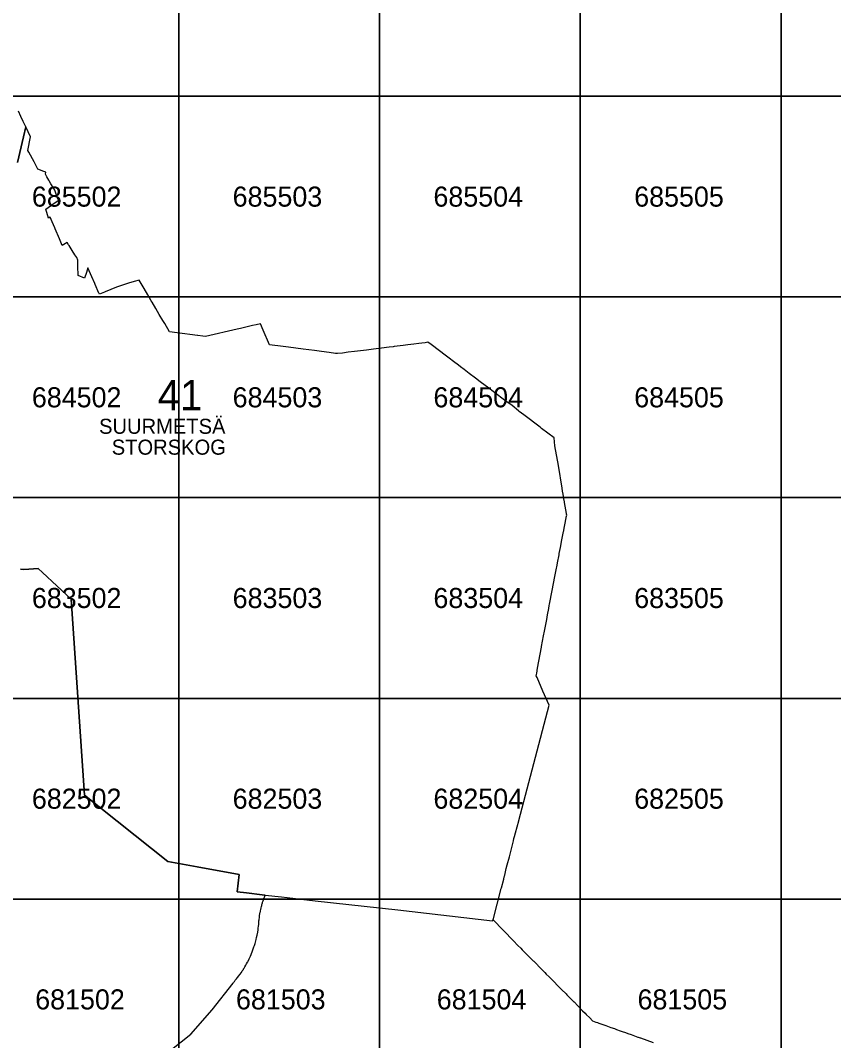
# Model space of a CAD drawing. Extents: x 25485000 to 25520000, y 6656775 to 6690000.
# Drawn here: x 25502211 to 25506262, y 6681295 to 6686378 of the extents above; entities that cross this region are included whole.
import ezdxf

# ---------------------------------------------------------------- set-up
doc = ezdxf.new("R2010")
doc.units = 0
doc.layers.add('Level 63', color=7, linetype='Continuous')

msp = doc.modelspace()

# ---------------------------------------------------------------- linework, layer by layer
at = {"layer": 'Level 63'}
for points in [[(25502000, 6686000), (25503000, 6686000), (25503000, 6687000), (25502000, 6687000)], [(25503000, 6686000), (25504000, 6686000), (25504000, 6687000), (25503000, 6687000)], [(25504000, 6686000), (25505000, 6686000), (25505000, 6687000), (25504000, 6687000)], [(25505000, 6686000), (25506000, 6686000), (25506000, 6687000), (25505000, 6687000)], [(25506000, 6686000), (25507000, 6686000), (25507000, 6687000), (25506000, 6687000)], [(25502000, 6685000), (25503000, 6685000), (25503000, 6686000), (25502000, 6686000)], [(25503000, 6685000), (25504000, 6685000), (25504000, 6686000), (25503000, 6686000)], [(25504000, 6685000), (25505000, 6685000), (25505000, 6686000), (25504000, 6686000)], [(25505000, 6685000), (25506000, 6685000), (25506000, 6686000), (25505000, 6686000)], [(25506000, 6685000), (25507000, 6685000), (25507000, 6686000), (25506000, 6686000)], [(25502000, 6684000), (25503000, 6684000), (25503000, 6685000), (25502000, 6685000)], [(25503000, 6684000), (25504000, 6684000), (25504000, 6685000), (25503000, 6685000)], [(25504000, 6684000), (25505000, 6684000), (25505000, 6685000), (25504000, 6685000)], [(25505000, 6684000), (25506000, 6684000), (25506000, 6685000), (25505000, 6685000)], [(25506000, 6684000), (25507000, 6684000), (25507000, 6685000), (25506000, 6685000)], [(25502000, 6683000), (25503000, 6683000), (25503000, 6684000), (25502000, 6684000)], [(25503000, 6683000), (25504000, 6683000), (25504000, 6684000), (25503000, 6684000)], [(25504000, 6683000), (25505000, 6683000), (25505000, 6684000), (25504000, 6684000)], [(25505000, 6683000), (25506000, 6683000), (25506000, 6684000), (25505000, 6684000)], [(25506000, 6683000), (25507000, 6683000), (25507000, 6684000), (25506000, 6684000)], [(25502000, 6682000), (25503000, 6682000), (25503000, 6683000), (25502000, 6683000)], [(25503000, 6682000), (25504000, 6682000), (25504000, 6683000), (25503000, 6683000)], [(25504000, 6682000), (25505000, 6682000), (25505000, 6683000), (25504000, 6683000)], [(25505000, 6682000), (25506000, 6682000), (25506000, 6683000), (25505000, 6683000)], [(25506000, 6682000), (25507000, 6682000), (25507000, 6683000), (25506000, 6683000)], [(25502000, 6681000), (25503000, 6681000), (25503000, 6682000), (25502000, 6682000)], [(25503000, 6681000), (25504000, 6681000), (25504000, 6682000), (25503000, 6682000)], [(25504000, 6681000), (25505000, 6681000), (25505000, 6682000), (25504000, 6682000)], [(25505000, 6681000), (25506000, 6681000), (25506000, 6682000), (25505000, 6682000)], [(25506000, 6681000), (25507000, 6681000), (25507000, 6682000), (25506000, 6682000)]]:
    msp.add_lwpolyline(points, close=True, dxfattribs=at)
for points in [[(25502197.7, 6685669.2), (25502227.1, 6685798.4), (25502238.5, 6685848.3), (25502231.7, 6685861.4), (25502225.7, 6685874.3), (25502214, 6685899.6), (25502202.2, 6685925)], [(25502211.4, 6683643.4), (25502228.6, 6683641.7), (25502253.1, 6683643.3), (25502300.5, 6683646.6), (25502321.2, 6683627.4), (25502463.8, 6683494.7), (25502531, 6682518), (25502946.3, 6682187.1), (25503092.3, 6682160.1), (25503300.4, 6682121.7), (25503291, 6682035.7), (25503337, 6682030.4), (25503414.7, 6682021.3), (25503430.1, 6682020), (25503511.5, 6682011.1), (25503539.7, 6682007.6), (25503680.1, 6681991.8), (25504091.9, 6681945.4), (25504563.5, 6681892.2), (25504565.2, 6681895.6), (25504606.4, 6682053.2), (25504607.2, 6682056.3), (25504618.4, 6682098.5), (25504618.8, 6682100.1), (25504622.8, 6682115.4), (25504623.5, 6682118.2), (25504629.6, 6682143.9), (25504631.5, 6682151.6), (25504636.2, 6682171.1), (25504646.6, 6682210.8), (25504656.9, 6682250.7), (25504667.1, 6682290.4), (25504669.7, 6682301.3), (25504672.5, 6682312.3), (25504677, 6682329.5), (25504693.1, 6682389.8), (25504693.3, 6682391), (25504768.4, 6682674.6), (25504845.6, 6682965.9), (25504814, 6683035.3), (25504784.5, 6683104.2), (25504780.8, 6683112.8), (25504783.2, 6683125.9), (25504787.6, 6683149.7), (25504807.1, 6683255.4), (25504807.5, 6683257.7), (25504817.3, 6683311.2), (25504821.7, 6683335.4), (25504832.6, 6683393.5), (25504836.6, 6683416.4), (25504842.6, 6683447.6), (25504845.4, 6683462.6), (25504846.7, 6683469.5), (25504859.9, 6683537.6), (25504866.5, 6683572), (25504873.1, 6683606.3), (25504879.8, 6683640.6), (25504884.3, 6683663.8), (25504886.4, 6683675), (25504894.2, 6683715.6), (25504894.7, 6683718.3), (25504895.3, 6683721), (25504901.1, 6683750.9), (25504908.7, 6683790.3), (25504916.7, 6683832), (25504917.2, 6683834.5), (25504917.7, 6683837), (25504919.7, 6683847.6), (25504923, 6683864.8), (25504929.9, 6683900.1), (25504930.4, 6683903.1), (25504932.3, 6683912.8), (25504931.1, 6683916.9), (25504930.9, 6683921.1), (25504921.2, 6683976.3), (25504920.9, 6683980.4), (25504920.2, 6683984.5), (25504914.6, 6684017.5), (25504911.7, 6684033), (25504909, 6684047.6), (25504891, 6684160.1), (25504873.2, 6684258.4), (25504869.8, 6684297.7), (25504807.3, 6684345), (25504800.6, 6684350.8), (25504718.5, 6684412.4), (25504695.5, 6684429.9), (25504691.4, 6684433), (25504660.9, 6684458.6), (25504648.5, 6684468.2), (25504630.4, 6684479.2), (25504543.9, 6684545.1), (25504501.8, 6684577.1), (25504478, 6684595.2), (25504447, 6684618.8), (25504421.7, 6684638.2), (25504403.4, 6684652), (25504385, 6684666), (25504381.9, 6684668.4), (25504333.5, 6684705.2), (25504256.9, 6684763.5), (25504241.2, 6684775.5), (25504226.9, 6684772.1), (25504211, 6684770), (25504196.1, 6684768), (25504171, 6684764.8), (25504141.4, 6684761.1), (25504117.5, 6684758.1), (25504088.7, 6684754.5), (25504072.7, 6684752.8), (25504068.1, 6684751.8), (25504047.4, 6684749.3), (25504009.9, 6684744.7), (25503969.4, 6684739.7), (25503934.8, 6684735.4), (25503905.1, 6684731.7), (25503875.3, 6684728), (25503844.5, 6684724.2), (25503815.7, 6684720.6), (25503789.9, 6684717.5), (25503780.7, 6684718.7), (25503748.6, 6684722.9), (25503710.7, 6684727.9), (25503676.1, 6684732.5), (25503648.4, 6684736.2), (25503619.2, 6684740), (25503582.4, 6684744.9), (25503546, 6684749.7), (25503519.6, 6684753.2), (25503452.3, 6684762.1), (25503420.5, 6684835), (25503406.6, 6684866.7), (25503386.2, 6684861.8), (25503366.7, 6684857.3), (25503347.3, 6684852.7), (25503327.8, 6684848.1), (25503308.3, 6684843.5), (25503290.7, 6684839.3), (25503133.3, 6684803), (25503119.5, 6684805), (25503095.3, 6684808.6), (25503094.1, 6684808.7), (25502992.9, 6684820.7), (25502954.4, 6684826.1), (25502930.3, 6684867.1), (25502921.1, 6684882.7), (25502903.2, 6684913), (25502885.4, 6684943.2), (25502867.5, 6684973.3), (25502862.8, 6684981.2), (25502845.5, 6685010.5), (25502827.1, 6685041.4), (25502802.6, 6685082.8), (25502778.2, 6685076.7), (25502749.5, 6685069.2), (25502720.2, 6685059.1), (25502690.8, 6685048.4), (25502662.2, 6685036.5), (25502633.6, 6685025.3), (25502629.4, 6685023.6), (25502604.9, 6685014), (25502603.1, 6685017.3), (25502602.7, 6685018.2), (25502583.4, 6685062.5), (25502581.4, 6685067), (25502567, 6685100.8), (25502547.5, 6685144.3), (25502540.1, 6685121.9), (25502530.6, 6685093.6), (25502498.6, 6685107.6), (25502498.5, 6685117.9), (25502498.2, 6685142.4), (25502498.1, 6685144.5), (25502497.5, 6685183.5), (25502492.5, 6685196.1), (25502482.5, 6685209.8), (25502469.5, 6685231.2), (25502453.8, 6685257), (25502452.7, 6685258.7), (25502451.7, 6685260.3), (25502444.4, 6685271.3), (25502419.7, 6685256.1), (25502406.9, 6685289.3), (25502385, 6685338.8), (25502382.9, 6685343.6), (25502370.2, 6685374), (25502360.2, 6685397.9), (25502350.9, 6685392.4), (25502338.3, 6685438), (25502349.7, 6685446), (25502372.6, 6685461.9), (25502398.7, 6685480.1), (25502401.4, 6685482), (25502395.1, 6685497.4), (25502388.8, 6685512.9), (25502387.4, 6685517.2), (25502382.5, 6685531.8), (25502366.2, 6685559), (25502363.6, 6685563.3), (25502354.3, 6685579.3), (25502352.2, 6685582.7), (25502343.7, 6685598), (25502335.9, 6685611.5), (25502337.7, 6685621.4), (25502327.4, 6685625), (25502299, 6685635.9), (25502281.3, 6685669.1), (25502279.2, 6685673.1), (25502253.3, 6685721.6), (25502248.6, 6685730.5), (25502261.4, 6685797.3), (25502238.5, 6685848.3), (25502227.1, 6685798.4), (25502197.7, 6685669.2)], [(25502907.5, 6681205.9), (25503060.1, 6681327.4), (25503166, 6681447.5), (25503270.7, 6681581.2), (25503273.1, 6681584.1), (25503274.3, 6681585.8), (25503277, 6681589.2), (25503281.8, 6681595.2), (25503284.9, 6681599), (25503286, 6681600.3), (25503287.6, 6681602.3), (25503293.3, 6681609.3), (25503299.5, 6681617.4), (25503303.7, 6681623.2), (25503311.8, 6681634.5), (25503316.5, 6681641.5), (25503319, 6681645.3), (25503321.7, 6681649.4), (25503323, 6681651.5), (25503325.3, 6681655.2), (25503329.9, 6681662.7), (25503334.5, 6681670.6), (25503337.8, 6681676.6), (25503342.7, 6681685.7), (25503343.8, 6681687.8), (25503345.3, 6681690.6), (25503350.7, 6681701.5), (25503356.7, 6681714.5), (25503365.7, 6681736.1), (25503374.7, 6681761), (25503377.1, 6681768.3), (25503380.1, 6681778.3), (25503385.4, 6681798), (25503387.9, 6681808.7), (25503390.2, 6681819.5), (25503393.2, 6681835.3), (25503394.9, 6681846.3), (25503396.1, 6681855.4), (25503397.2, 6681864.3), (25503398.1, 6681872.9), (25503398.3, 6681877.4), (25503398.5, 6681879.9), (25503398.6, 6681880.7), (25503399.1, 6681886.5), (25503399.3, 6681889), (25503399.4, 6681890.2), (25503399.5, 6681890.7), (25503399.7, 6681892.9), (25503399.8, 6681893.8), (25503400.3, 6681898.8), (25503401.5, 6681907.7), (25503402.1, 6681912.6), (25503402.5, 6681915.3), (25503402.9, 6681917.8), (25503404.3, 6681926.3), (25503405.7, 6681934), (25503406.5, 6681938.1), (25503407.2, 6681941.2), (25503408.6, 6681948.3), (25503410.6, 6681956.7), (25503412, 6681962.5), (25503413.2, 6681967.1), (25503413.9, 6681969.8), (25503415.9, 6681977.3), (25503416.5, 6681979.5), (25503417.9, 6681984.2), (25503419.8, 6681990.3), (25503421.4, 6681995.2), (25503422.9, 6681999.8), (25503424, 6682003.2), (25503425.3, 6682006.9), (25503426.4, 6682010.1), (25503428.2, 6682015.1), (25503429.1, 6682017.3), (25503430.1, 6682020), (25503414.7, 6682021.3), (25503337, 6682030.4), (25503291, 6682035.7), (25503300.4, 6682121.7), (25503092.3, 6682160.1), (25502946.3, 6682187.1), (25502531, 6682518), (25502463.8, 6683494.7), (25502321.2, 6683627.4), (25502300.5, 6683646.6), (25502253.1, 6683643.3), (25502228.6, 6683641.7), (25502211.4, 6683643.4)], [(25502907.5, 6681205.9), (25503060.1, 6681327.4), (25503166, 6681447.5), (25503270.7, 6681581.2), (25503273.1, 6681584.1), (25503274.3, 6681585.8), (25503277, 6681589.2), (25503281.8, 6681595.2), (25503284.9, 6681599), (25503286, 6681600.3), (25503287.6, 6681602.3), (25503293.3, 6681609.3), (25503299.5, 6681617.4), (25503303.7, 6681623.2), (25503311.8, 6681634.5), (25503316.5, 6681641.5), (25503319, 6681645.3), (25503321.7, 6681649.4), (25503323, 6681651.5), (25503325.3, 6681655.2), (25503329.9, 6681662.7), (25503334.5, 6681670.6), (25503337.8, 6681676.6), (25503342.7, 6681685.7), (25503343.8, 6681687.8), (25503345.3, 6681690.6), (25503350.7, 6681701.5), (25503356.7, 6681714.5), (25503365.7, 6681736.1), (25503374.7, 6681761), (25503377.1, 6681768.3), (25503380.1, 6681778.3), (25503385.4, 6681798), (25503387.9, 6681808.7), (25503390.2, 6681819.5), (25503393.2, 6681835.3), (25503394.9, 6681846.3), (25503396.1, 6681855.4), (25503397.2, 6681864.3), (25503398.1, 6681872.9), (25503398.3, 6681877.4), (25503398.5, 6681879.9), (25503398.6, 6681880.7), (25503399.1, 6681886.5), (25503399.3, 6681889), (25503399.4, 6681890.2), (25503399.5, 6681890.7), (25503399.7, 6681892.9), (25503399.8, 6681893.8), (25503400.3, 6681898.8), (25503401.5, 6681907.7), (25503402.1, 6681912.6), (25503402.5, 6681915.3), (25503402.9, 6681917.8), (25503404.3, 6681926.3), (25503405.7, 6681934), (25503406.5, 6681938.1), (25503407.2, 6681941.2), (25503408.6, 6681948.3), (25503410.6, 6681956.7), (25503412, 6681962.5), (25503413.2, 6681967.1), (25503413.9, 6681969.8), (25503415.9, 6681977.3), (25503416.5, 6681979.5), (25503417.9, 6681984.2), (25503419.8, 6681990.3), (25503421.4, 6681995.2), (25503422.9, 6681999.8), (25503424, 6682003.2), (25503425.3, 6682006.9), (25503426.4, 6682010.1), (25503428.2, 6682015.1), (25503429.1, 6682017.3), (25503430.1, 6682020), (25503511.5, 6682011.1), (25503539.7, 6682007.6), (25503680.1, 6681991.8), (25504091.9, 6681945.4), (25504563.5, 6681892.2), (25504565.2, 6681895.6), (25504667.5, 6681791.4), (25504689.5, 6681769), (25504703.4, 6681755.1), (25504711.2, 6681747.2), (25504732.5, 6681725.6), (25504757.3, 6681700.3), (25504759.4, 6681698.4), (25504759.8, 6681697.7), (25504765.6, 6681692.1), (25504768, 6681689.7), (25504786, 6681671.5), (25504789.2, 6681668.3), (25504809.9, 6681647.3), (25504822.9, 6681634), (25504830.8, 6681625.8), (25504844.1, 6681612.7), (25504851.9, 6681604.9), (25504867.5, 6681589.3), (25504888.6, 6681568.1), (25504902.2, 6681554.4), (25504910.5, 6681546.1), (25504926, 6681530.5), (25504929.4, 6681526.9), (25504933.6, 6681522.2), (25504942.9, 6681513.2), (25504967.6, 6681488.6), (25504969.1, 6681487), (25504987.9, 6681467.6), (25504990.8, 6681464.5), (25505011.3, 6681443.7), (25505024, 6681430.7), (25505029.6, 6681425.1), (25505047, 6681407.3), (25505061.1, 6681393.2), (25505077.2, 6681387.2), (25505085.9, 6681384), (25505093, 6681381.5), (25505117, 6681373), (25505126.5, 6681369.5), (25505135.3, 6681366.5), (25505151.8, 6681360.5), (25505170.1, 6681354.1), (25505179.8, 6681350.6), (25505197.9, 6681344.1), (25505208.4, 6681340.3), (25505225.4, 6681334.2), (25505236.7, 6681330.3), (25505252.7, 6681324.6), (25505286, 6681312.4), (25505287.2, 6681312), (25505287.6, 6681311.9), (25505297.4, 6681308.6), (25505300.4, 6681307.6), (25505363.7, 6681285)]]:
    msp.add_lwpolyline(points, dxfattribs=at)

# ---------------------------------------------------------------- texts
for s, height, p in [('685502', 100, (25502268.5, 6685450)), ('685503', 100, (25503268.5, 6685450)), ('685504', 100, (25504268.5, 6685450)), ('685505', 100, (25505268.5, 6685450)), ('684502', 100, (25502268.5, 6684450)), ('41', 150, (25502895, 6684435.7)), ('684503', 100, (25503268.5, 6684450)), ('684504', 100, (25504268.5, 6684450)), ('684505', 100, (25505268.5, 6684450)), ('SUURMETSÄ', 75, (25502603.1, 6684318)), ('STORSKOG', 75, (25502666.3, 6684214)), ('683502', 100, (25502268.5, 6683450)), ('683503', 100, (25503268.5, 6683450)), ('683504', 100, (25504268.5, 6683450)), ('683505', 100, (25505268.5, 6683450)), ('682502', 100, (25502268.5, 6682450)), ('682503', 100, (25503268.5, 6682450)), ('682504', 100, (25504268.5, 6682450)), ('682505', 100, (25505268.5, 6682450)), ('681502', 100, (25502285.1, 6681450)), ('681503', 100, (25503285.1, 6681450)), ('681504', 100, (25504285.1, 6681450)), ('681505', 100, (25505285.1, 6681450))]:
    msp.add_text(s, height=height, dxfattribs=at).set_placement(p)

doc.saveas('drawing.dxf')
